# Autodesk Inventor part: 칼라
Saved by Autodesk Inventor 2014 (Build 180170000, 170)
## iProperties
Created: 2025-09
Part Number: 칼라
Material: 일반
Document SubType Name: Modeling
Designer: dg
Density: 1 g/cm^3
Appearance: 기본값
Author: dg
Author: jhkim
Creation Date: 2025-09-02
Sending System: Autodesk Inventor 2026
Preprocessor: ST-DEVELOPER v20.1
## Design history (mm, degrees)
node "칼라1"
node "솔리드1"
node "기준1"
